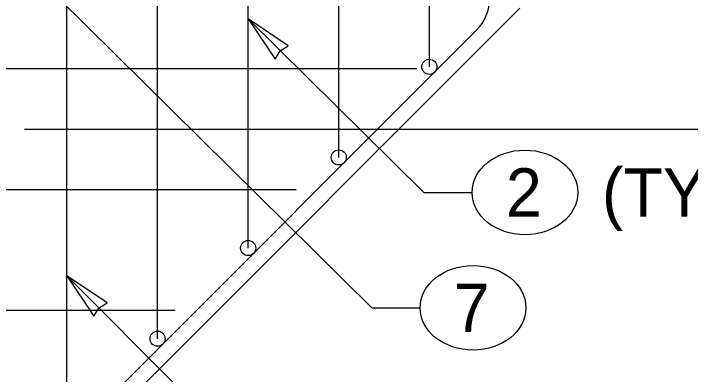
# Model space of a CAD drawing. Extents: x 99862 to 103151, y 100000 to 102076.
# Drawn here: x 101842.6 to 102066.7, y 101029.5 to 101148.9 of the extents above; entities that cross this region are included whole.
import ezdxf

# ---------------------------------------------------------------- set-up
doc = ezdxf.new("R2010")
doc.units = 0
for name, color, linetype in [('Level 10', 7, 'Continuous'), ('Level 15', 7, 'Continuous'), ('Level 2', 7, 'Continuous'), ('Level 20', 7, 'Continuous')]:
    doc.layers.add(name, color=color, linetype=linetype)

msp = doc.modelspace()

# ---------------------------------------------------------------- linework, layer by layer
at = {"layer": 'Level 10'}
for p, q in [((101860.29, 101011.32), (101860.29, 101318.21)), ((101890.29, 101041.32), (101890.29, 101318.21)), ((101920.29, 101071.32), (101920.29, 101318.21)), ((101950.29, 101101.32), (101950.29, 101318.21)), ((101950.29, 101101.32), (101950.29, 101318.21)), ((101980.29, 101131.32), (101980.29, 101318.21)), ((101699.47, 100846.97), (101995.89, 101143.39)), ((101753.62, 101130.72), (101976.14, 101130.72)), ((101753.62, 101130.72), (101976.14, 101130.72)), ((101753.62, 101090.72), (101936.14, 101090.72)), ((101753.62, 101050.72), (101896.14, 101050.72))]:
    msp.add_line(p, q, dxfattribs=at)
for centre in [(101980.29, 101131.32), (101980.29, 101131.32), (101950.29, 101101.32), (101950.29, 101101.32), (101920.29, 101071.32), (101920.29, 101071.32), (101890.29, 101041.32), (101890.29, 101041.32)]:
    msp.add_circle(centre, 2.5, dxfattribs=at)
msp.add_arc((101985.29, 101154), 15, 315, 0, dxfattribs=at)
at = {"layer": 'Level 15'}
for p, q in [((101819.9, 101191.19), (101961.24, 101051.54)), ((101819.9, 101191.19), (101961.24, 101051.54)), ((101920.29, 101147.17), (101978.43, 101089.73)), ((101920.29, 101147.17), (101978.43, 101089.73)), ((101846.29, 101110.71), (102186.29, 101110.71)), ((101846.29, 101110.71), (102186.29, 101110.71)), ((101978.43, 101089.73), (101994.43, 101089.73)), ((101978.43, 101089.73), (101994.43, 101089.73)), ((101860.29, 101062.08), (101916.03, 101006.33)), ((101860.29, 101062.08), (101916.03, 101006.33)), ((101961.24, 101051.54), (101977.24, 101051.54)), ((101961.24, 101051.54), (101977.24, 101051.54))]:
    msp.add_line(p, q, dxfattribs=at)
for points in [[(101920.29, 101147.17), (101929.22, 101133.87), (101930.89, 101136.56), (101933.59, 101138.23)], [(101860.29, 101062.08), (101869.22, 101048.78), (101870.89, 101051.47), (101873.59, 101053.14)]]:
    msp.add_lwpolyline(points, close=True, dxfattribs=at)
at = {"layer": 'Level 2'}
msp.add_line((101830.29, 100970.72), (102010.29, 101150.71), dxfattribs=at)
msp.add_line((101830.29, 100970.72), (102010.29, 101150.71), dxfattribs=at)
at = {"layer": 'Level 20'}
for centre in [(102011.93, 101089.73), (101994.74, 101051.54)]:
    msp.add_ellipse(centre, major_axis=(-17.5, 0), ratio=0.8, dxfattribs=at)

# ---------------------------------------------------------------- texts
for s, p in [('(TYP.)', (102037.43, 101081.73)), ('2', (102005.63, 101081.73)), ('7', (101988.34, 101043.54))]:
    msp.add_text(s, height=16, dxfattribs=at).set_placement(p)

doc.saveas('drawing.dxf')
